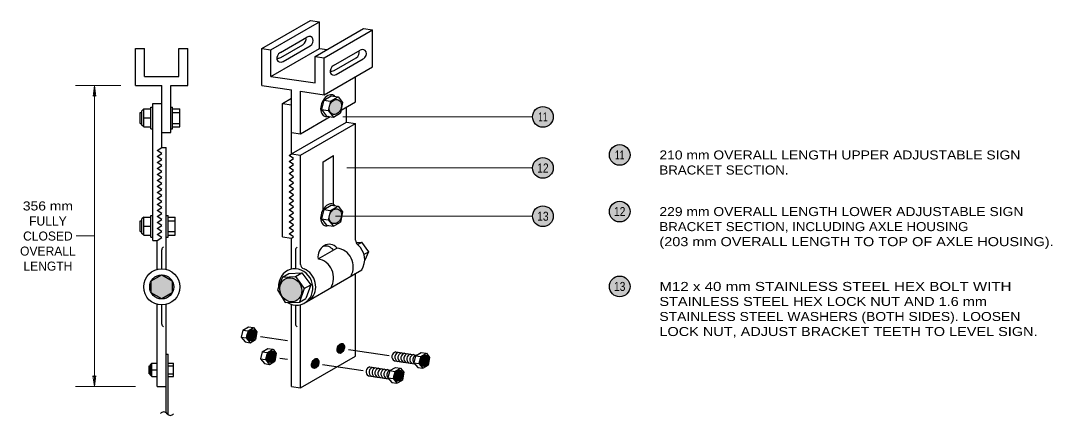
# Model space of a CAD drawing. Extents: x 312583 to 312853, y 144376 to 144586.
# Drawn here: x 312635.8 to 312721.6, y 144491.8 to 144524.7 of the extents above; entities that cross this region are included whole.
import ezdxf
from ezdxf.enums import TextEntityAlignment as Align

# ---------------------------------------------------------------- set-up
doc = ezdxf.new("R2010")
doc.units = 0
doc.header["$LTSCALE"] = 0.3
doc.layers.add('1', color=7, linetype='Continuous', lineweight=25)
doc.layers.add('2', color=7, linetype='Continuous', lineweight=13)

msp = doc.modelspace()

# ---------------------------------------------------------------- hatches: boundary and pattern name
at = {"layer": '1'}
h = msp.add_hatch(color=256, dxfattribs=at)
edge = h.paths.add_edge_path()
edge.add_ellipse((312661.9638, 144517.4761), major_axis=(0.2406, 0.5922), ratio=0.761491, start_angle=0, end_angle=360)
h = msp.add_hatch(color=256, dxfattribs=at)
edge = h.paths.add_edge_path()
edge.add_ellipse((312661.9638, 144508.3941), major_axis=(0.2406, 0.5922), ratio=0.761491, start_angle=0, end_angle=360)
for points in [[(312648.5336, 144502.5181, 1), (312646.5336, 144502.5181, 1)], [(312647.5336, 144503.5181), (312648.3997, 144503.0181), (312648.3997, 144502.0181), (312647.5336, 144501.5181), (312646.6676, 144502.0181), (312646.6676, 144503.0181)]]:
    msp.add_hatch(color=256, dxfattribs=at).paths.add_polyline_path(points)
h = msp.add_hatch(color=256, dxfattribs=at)
edge = h.paths.add_edge_path()
edge.add_ellipse((312658.2586, 144502.281), major_axis=(-0.3821, 0.9403), ratio=0.8873452, start_angle=0, end_angle=360)
h = msp.add_hatch(color=256, dxfattribs=at)
edge = h.paths.add_edge_path()
edge.add_ellipse((312655.0001, 144498.5047), major_axis=(0.1805, 0.4441), ratio=0.761491, start_angle=0, end_angle=360)
h = msp.add_hatch(color=256, dxfattribs=at)
edge = h.paths.add_edge_path()
edge.add_ellipse((312655.0001, 144498.5047), major_axis=(0.11, 0.2708), ratio=0.6087617, start_angle=0, end_angle=360)
h = msp.add_hatch(color=256, dxfattribs=at)
edge = h.paths.add_edge_path()
edge.add_ellipse((312662.4171, 144497.4067), major_axis=(0.1639, 0.4034), ratio=0.649846, start_angle=0, end_angle=360)
h = msp.add_hatch(color=256, dxfattribs=at)
edge = h.paths.add_edge_path()
edge.add_ellipse((312656.6117, 144496.7038), major_axis=(0.1805, 0.4441), ratio=0.761491, start_angle=0, end_angle=360)
h = msp.add_hatch(color=256, dxfattribs=at)
edge = h.paths.add_edge_path()
edge.add_ellipse((312656.6117, 144496.7038), major_axis=(0.11, 0.2708), ratio=0.6087617, start_angle=0, end_angle=360)
h = msp.add_hatch(color=256, dxfattribs=at)
edge = h.paths.add_edge_path()
edge.add_ellipse((312660.2921, 144496.159), major_axis=(0.1639, 0.4034), ratio=0.649846, start_angle=0, end_angle=360)
h = msp.add_hatch(color=256, dxfattribs=at)
edge = h.paths.add_edge_path()
edge.add_ellipse((312669.3588, 144496.3789), major_axis=(0.1805, 0.4441), ratio=0.761491, start_angle=0, end_angle=360)
h = msp.add_hatch(color=256, dxfattribs=at)
edge = h.paths.add_edge_path()
edge.add_ellipse((312667.2051, 144495.1355), major_axis=(0.1805, 0.4441), ratio=0.761491, start_angle=0, end_angle=360)
at = {"layer": '2'}
for points in [[(312680.0731, 144516.654, 1), (312678.3539, 144516.654, 1)], [(312686.4534, 144513.4875, 1), (312684.7342, 144513.4875, 1)], [(312680.0731, 144512.4048, 1), (312678.3539, 144512.4048, 1)], [(312680.0731, 144508.3941, 1), (312678.3539, 144508.3941, 1)], [(312686.4534, 144508.7813, 1), (312684.7342, 144508.7813, 1)], [(312686.4534, 144502.5587, 1), (312684.7342, 144502.5587, 1)]]:
    msp.add_hatch(color=256, dxfattribs=at).paths.add_polyline_path(points)

# ---------------------------------------------------------------- linework, layer by layer
at = {"layer": '1'}
for p, q in [((312655.858, 144522.3287), (312659.8879, 144524.6554)), ((312656.608, 144522.2176), (312660.638, 144524.5443)), ((312659.8879, 144524.6554), (312660.638, 144524.5443)), ((312660.638, 144522.3421), (312660.638, 144524.5443)), ((312660.2841, 144521.6731), (312664.3142, 144523.9999)), ((312664.3142, 144523.9999), (312665.0641, 144523.8888)), ((312657.3943, 144522.0035), (312659.5982, 144523.2759)), ((312645.3586, 144519.2653), (312645.3586, 144522.3287)), ((312645.3586, 144522.3287), (312646.1086, 144522.3287)), ((312646.1086, 144520.0153), (312646.1086, 144522.3287)), ((312648.9586, 144520.0153), (312648.9586, 144522.3287)), ((312648.9586, 144522.3287), (312649.7086, 144522.3287)), ((312649.7086, 144519.2653), (312649.7086, 144522.3287)), ((312655.858, 144519.2653), (312655.858, 144522.3287)), ((312655.858, 144522.3287), (312656.608, 144522.2176)), ((312656.608, 144520.0153), (312660.638, 144522.3421)), ((312656.608, 144520.0153), (312656.608, 144522.2176)), ((312657.4283, 144521.5902), (312659.2663, 144522.6513)), ((312657.6159, 144521.2654), (312659.8633, 144522.5629)), ((312660.638, 144522.3421), (312661.2785, 144522.2472)), ((312661.8204, 144520.9174), (312664.0244, 144522.1899)), ((312660.2841, 144519.4709), (312660.2841, 144521.6731)), ((312661.0341, 144518.4987), (312661.0341, 144521.5621)), ((312661.8545, 144520.5041), (312663.6924, 144521.5652)), ((312662.042, 144520.1793), (312664.2894, 144521.4768)), ((312645.3586, 144519.2653), (312647.5336, 144519.2653)), ((312646.1086, 144520.0153), (312648.9586, 144520.0153)), ((312648.2836, 144519.2653), (312649.7086, 144519.2653)), ((312655.858, 144519.2653), (312658.3203, 144518.9007)), ((312656.608, 144520.0153), (312660.2841, 144519.4709)), ((312663.6493, 144517.8979), (312663.6493, 144520.0086)), ((312658.3203, 144513.5713), (312658.3203, 144518.9007)), ((312659.0703, 144515.2542), (312659.0703, 144518.7896)), ((312659.0703, 144518.7896), (312661.0341, 144518.4987)), ((312661.0035, 144518.0396), (312661.6293, 144518.4009)), ((312661.6292, 144518.4009), (312662.185, 144518.3186)), ((312646.7836, 144517.7653), (312647.5336, 144517.7653)), ((312646.7836, 144506.3653), (312646.7836, 144517.7653)), ((312657.5703, 144517.7653), (312658.3203, 144518.1983)), ((312657.5703, 144517.7653), (312658.3203, 144517.6543)), ((312657.5703, 144506.6824), (312657.5703, 144517.7653)), ((312661.0035, 144518.0396), (312660.8034, 144517.2575)), ((312662.4389, 144517.1991), (312663.6493, 144517.8979)), ((312645.7336, 144516.1153), (312645.7336, 144517.0153)), ((312645.7336, 144517.0153), (312645.8836, 144517.0153)), ((312646.0336, 144517.3153), (312645.8836, 144517.1653)), ((312645.8836, 144515.9653), (312645.8836, 144517.1653)), ((312646.0336, 144515.8153), (312646.0336, 144517.3153)), ((312646.0336, 144517.3153), (312646.6336, 144517.3153)), ((312648.2836, 144517.4653), (312648.4336, 144517.4653)), ((312648.4336, 144515.6653), (312648.4336, 144517.4653)), ((312648.4336, 144517.3153), (312649.0336, 144517.3153)), ((312648.4336, 144517.0153), (312649.0336, 144517.0153)), ((312649.0336, 144515.8153), (312649.0336, 144517.3153)), ((312659.0703, 144515.2542), (312661.538, 144516.679)), ((312660.8034, 144517.2575), (312661.3696, 144517.1737)), ((312661.8044, 144516.6395), (312662.4029, 144516.9851)), ((312645.7336, 144516.1153), (312645.8836, 144516.1153)), ((312646.0336, 144515.8153), (312645.8836, 144515.9653)), ((312646.0336, 144516.5653), (312646.6336, 144516.5653)), ((312646.0336, 144515.8153), (312646.6336, 144515.8153)), ((312648.4336, 144516.1153), (312649.0336, 144516.1153)), ((312648.4336, 144515.8153), (312649.0336, 144515.8153)), ((312662.8993, 144516.2149), (312663.6493, 144516.1039)), ((312663.6493, 144506.3962), (312663.6493, 144516.1039)), ((312646.6336, 144515.6653), (312646.7836, 144515.6653)), ((312648.2836, 144515.6653), (312648.4336, 144515.6653)), ((312658.3203, 144515.3653), (312659.0703, 144515.2542)), ((312647.5336, 144514.1153), (312647.9086, 144514.1153)), ((312647.9086, 144503.9704), (312647.9086, 144514.1153)), ((312659.0703, 144504.3901), (312659.0703, 144513.4602)), ((312661.813, 144509.3692), (312661.813, 144513.4318)), ((312661.0035, 144508.9576), (312660.8034, 144508.1755)), ((312661.0035, 144508.9576), (312661.6293, 144509.3189)), ((312661.6292, 144509.3189), (312662.185, 144509.2366)), ((312646.0336, 144508.3153), (312645.8836, 144508.1653)), ((312645.8836, 144506.9653), (312645.8836, 144508.1653)), ((312646.0336, 144506.8153), (312646.0336, 144508.3153)), ((312646.0336, 144508.3153), (312646.6336, 144508.3153)), ((312647.9086, 144508.4653), (312648.0586, 144508.4653)), ((312648.0586, 144506.6653), (312648.0586, 144508.4653)), ((312648.0586, 144508.3153), (312648.6586, 144508.3153)), ((312648.6586, 144506.8153), (312648.6586, 144508.3153)), ((312660.8034, 144508.1755), (312661.3696, 144508.0917)), ((312645.7336, 144507.1153), (312645.7336, 144508.0153)), ((312645.7336, 144508.0153), (312645.8836, 144508.0153)), ((312646.0336, 144507.5653), (312646.6336, 144507.5653)), ((312648.0586, 144508.0153), (312648.6586, 144508.0153)), ((312661.8044, 144507.5575), (312662.4029, 144507.9031)), ((312645.7336, 144507.1153), (312645.8836, 144507.1153)), ((312646.0336, 144506.8153), (312645.8836, 144506.9653)), ((312646.0336, 144506.8153), (312646.6336, 144506.8153)), ((312646.6336, 144506.6653), (312646.7836, 144506.6653)), ((312647.9086, 144506.6653), (312648.0586, 144506.6653)), ((312648.0586, 144507.1153), (312648.6586, 144507.1153)), ((312648.0586, 144506.8153), (312648.6586, 144506.8153)), ((312657.5703, 144506.6824), (312658.3203, 144506.5713)), ((312658.3203, 144503.9925), (312658.3203, 144506.5713)), ((312646.7836, 144506.3653), (312647.1586, 144506.3653)), ((312647.1586, 144503.9704), (312647.1586, 144506.3653)), ((312647.5336, 144504.0181), (312647.5336, 144505.606)), ((312658.6501, 144505.5937), (312658.6501, 144504.0181)), ((312660.5289, 144504.848), (312662.097, 144505.7533)), ((312663.6876, 144506.2093), (312664.1458, 144506.2322)), ((312663.8062, 144506.0362), (312664.1458, 144506.2322)), ((312664.1458, 144506.2322), (312664.7292, 144505.4317)), ((312664.3439, 144505.2093), (312664.7292, 144505.4317)), ((312664.7292, 144505.4317), (312664.4027, 144504.7538)), ((312659.5549, 144501.2856), (312664.1529, 144503.9403)), ((312657.5627, 144503.3221), (312658.0998, 144503.6322)), ((312658.0998, 144503.6322), (312659.1831, 144503.6863)), ((312658.646, 144503.3762), (312659.1831, 144503.6863)), ((312663.6493, 144496.7589), (312663.6493, 144503.6495)), ((312663.6493, 144502.9771), (312663.6493, 144503.6495)), ((312659.3766, 144502.3737), (312659.9137, 144502.6838)), ((312658.9737, 144501.2433), (312659.5108, 144501.5534)), ((312647.1586, 144494.2385), (312647.1586, 144501.0657)), ((312647.5336, 144499.4302), (312647.5336, 144501.0181)), ((312647.9086, 144492.0507), (312647.9086, 144501.0657)), ((312658.3203, 144494.2263), (312658.3203, 144501.0717)), ((312658.6501, 144501.0082), (312658.6501, 144499.4326)), ((312659.0703, 144494.1152), (312659.0703, 144501.0461)), ((312654.2798, 144498.9274), (312654.1298, 144498.3408)), ((312654.2798, 144498.9274), (312654.7492, 144499.1984)), ((312654.7492, 144499.1984), (312655.166, 144499.1366)), ((312654.1298, 144498.3408), (312654.5545, 144498.2779)), ((312654.8806, 144497.8773), (312655.3294, 144498.1365)), ((312655.7474, 144498.3941), (312657.9988, 144498.0608)), ((312655.8914, 144497.1265), (312655.7414, 144496.5399)), ((312655.8914, 144497.1265), (312656.3608, 144497.3975)), ((312656.3608, 144497.3975), (312656.7776, 144497.3357)), ((312663.0431, 144497.3141), (312666.4291, 144496.8129)), ((312666.9895, 144497.1089), (312668.7255, 144496.8518)), ((312668.6385, 144496.8016), (312669.1079, 144497.0726)), ((312669.1079, 144497.0726), (312669.5247, 144497.0108)), ((312646.7086, 144496.1885), (312646.5961, 144496.076)), ((312646.7086, 144495.0635), (312646.7086, 144496.1885)), ((312646.7086, 144496.1885), (312647.1586, 144496.1885)), ((312647.9086, 144496.9385), (312648.0586, 144496.9385)), ((312648.0586, 144491.8994), (312648.0586, 144496.9385)), ((312648.0586, 144496.1885), (312648.5086, 144496.1885)), ((312648.5086, 144495.0635), (312648.5086, 144496.1885)), ((312655.7414, 144496.5399), (312656.1661, 144496.477)), ((312656.4922, 144496.0764), (312656.941, 144496.3356)), ((312657.359, 144496.5932), (312657.9988, 144496.4985)), ((312666.8725, 144496.368), (312668.5684, 144496.1168)), ((312668.6385, 144496.8016), (312668.4885, 144496.215)), ((312668.4885, 144496.215), (312668.9132, 144496.1521)), ((312646.4836, 144495.2885), (312646.4836, 144495.9635)), ((312646.4836, 144495.9635), (312646.5961, 144495.9635)), ((312646.4836, 144495.2885), (312646.5961, 144495.2885)), ((312646.5961, 144495.176), (312646.5961, 144496.076)), ((312646.7086, 144495.626), (312647.1586, 144495.626)), ((312648.0586, 144495.9635), (312648.5086, 144495.9635)), ((312648.0586, 144495.2885), (312648.5086, 144495.2885)), ((312660.8894, 144496.0706), (312664.2754, 144495.5694)), ((312664.8358, 144495.8655), (312666.5718, 144495.6084)), ((312666.4848, 144495.5581), (312666.3348, 144494.9716)), ((312666.4848, 144495.5581), (312666.9542, 144495.8291)), ((312666.9542, 144495.8291), (312667.371, 144495.7674)), ((312669.2393, 144495.7515), (312669.6881, 144496.0107)), ((312646.7086, 144495.0635), (312646.5961, 144495.176)), ((312646.7086, 144495.0635), (312647.1586, 144495.0635)), ((312648.0586, 144495.0635), (312648.5086, 144495.0635)), ((312664.7188, 144495.1246), (312666.4147, 144494.8734)), ((312666.3348, 144494.9716), (312666.7595, 144494.9087)), ((312667.0856, 144494.5081), (312667.5344, 144494.7672)), ((312647.1586, 144494.2385), (312647.9086, 144494.2385))]:
    msp.add_line(p, q, dxfattribs=at)
for points in [[(312660.2841, 144521.6731), (312661.0341, 144521.5621), (312665.0641, 144523.8888)], [(312661.0341, 144518.4987), (312665.0641, 144520.8255), (312665.0641, 144523.8888)], [(312647.1586, 144506.3653), (312647.5336, 144506.6153), (312647.1586, 144506.8653), (312647.5336, 144507.1153), (312647.1586, 144507.3653), (312647.5336, 144507.6153), (312647.1586, 144507.8653), (312647.5336, 144508.1153), (312647.1586, 144508.3653), (312647.5336, 144508.6153), (312647.1586, 144508.8653), (312647.5336, 144509.1153), (312647.1586, 144509.3653), (312647.5336, 144509.6153), (312647.1586, 144509.8653), (312647.5336, 144510.1153), (312647.1586, 144510.3653), (312647.5336, 144510.6153), (312647.1586, 144510.8653), (312647.5336, 144511.1153), (312647.1586, 144511.3653), (312647.5336, 144511.6153), (312647.1586, 144511.8653), (312647.5336, 144512.1153), (312647.1586, 144512.3653), (312647.5336, 144512.6153), (312647.1586, 144512.8653), (312647.5336, 144513.1153), (312647.1586, 144513.3653), (312647.5336, 144513.6153), (312647.1586, 144513.8653), (312647.5336, 144514.1153), (312647.5336, 144519.2653)], [(312647.5336, 144515.3653), (312648.2836, 144515.3653), (312648.2836, 144519.2653)], [(312661.0035, 144518.0396), (312661.5697, 144517.9558), (312662.1955, 144518.3171)], [(312661.5697, 144517.9558), (312661.3696, 144517.1737), (312661.8044, 144516.6395)], [(312662.1955, 144518.3171), (312662.5489, 144517.8545), (312662.4029, 144516.9851)], [(312646.6336, 144515.6653), (312646.6336, 144517.4653), (312646.7836, 144517.4653)], [(312658.3203, 144513.5713), (312662.8993, 144516.2149), (312662.8993, 144517.4649)], [(312660.8034, 144517.2575), (312661.2382, 144516.7234), (312661.8044, 144516.6395)], [(312658.3203, 144513.5713), (312659.0703, 144513.4602), (312663.6493, 144516.1039)], [(312647.1586, 144506.3653), (312647.5336, 144506.6153), (312647.1586, 144506.8653), (312647.5336, 144507.1153), (312647.1586, 144507.3653), (312647.5336, 144507.6153), (312647.1586, 144507.8653), (312647.5336, 144508.1153), (312647.1586, 144508.3653), (312647.5336, 144508.6153), (312647.1586, 144508.8653), (312647.5336, 144509.1153), (312647.1586, 144509.3653), (312647.5336, 144509.6153), (312647.1586, 144509.8653), (312647.5336, 144510.1153), (312647.1586, 144510.3653), (312647.5336, 144510.6153), (312647.1586, 144510.8653), (312647.5336, 144511.1153), (312647.1586, 144511.3653), (312647.5336, 144511.6153), (312647.1586, 144511.8653), (312647.5336, 144512.1153), (312647.1586, 144512.3653), (312647.5336, 144512.6153), (312647.1586, 144512.8653), (312647.5336, 144513.1153), (312647.1586, 144513.3653), (312647.5336, 144513.6153), (312647.1586, 144513.8653), (312647.5336, 144514.1153)], [(312658.3203, 144506.5713), (312658.4882, 144506.6833), (312658.1132, 144506.9333), (312658.4882, 144507.1833), (312658.1132, 144507.4333), (312658.4882, 144507.6833), (312658.1132, 144507.9333), (312658.4882, 144508.1833), (312658.1132, 144508.4333), (312658.4882, 144508.6833), (312658.1132, 144508.9333), (312658.4882, 144509.1833), (312658.1132, 144509.4333), (312658.4882, 144509.6833), (312658.1132, 144509.9333), (312658.4882, 144510.1833), (312658.1132, 144510.4333), (312658.4882, 144510.6833), (312658.1132, 144510.9333), (312658.4882, 144511.1833), (312658.1132, 144511.4333), (312658.4882, 144511.6833), (312658.1132, 144511.9333), (312658.4882, 144512.1833), (312658.1132, 144512.4333), (312658.4882, 144512.6833), (312658.1132, 144512.9333), (312658.4882, 144513.1833), (312658.1132, 144513.4333), (312658.3203, 144513.5713)], [(312660.938, 144508.9288), (312660.938, 144512.9266), (312661.813, 144513.4318)], [(312661.0035, 144508.9576), (312661.5697, 144508.8738), (312662.1955, 144509.2351)], [(312662.1955, 144509.2351), (312662.5489, 144508.7725), (312662.4029, 144507.9031)], [(312646.6336, 144506.6653), (312646.6336, 144508.4653), (312646.7836, 144508.4653)], [(312660.8034, 144508.1755), (312661.2382, 144507.6414), (312661.8044, 144507.5575)], [(312661.5697, 144508.8738), (312661.3696, 144508.0917), (312661.8044, 144507.5575)], [(312657.5627, 144503.3221), (312657.163, 144502.2657), (312657.8019, 144501.2266), (312658.9737, 144501.2433)], [(312657.5627, 144503.3221), (312658.646, 144503.3762), (312659.3766, 144502.3737), (312658.9737, 144501.2433)], [(312659.1831, 144503.6863), (312659.9137, 144502.6838), (312659.5108, 144501.5534)], [(312654.2798, 144498.9274), (312654.7045, 144498.8645), (312655.1738, 144499.1355)], [(312654.7045, 144498.8645), (312654.5545, 144498.2779), (312654.8806, 144497.8773)], [(312655.1738, 144499.1355), (312655.4389, 144498.7886), (312655.3294, 144498.1365)], [(312654.1298, 144498.3408), (312654.4559, 144497.9402), (312654.8806, 144497.8773)], [(312655.8914, 144497.1265), (312656.3161, 144497.0636), (312656.7854, 144497.3346)], [(312656.3161, 144497.0636), (312656.1661, 144496.477), (312656.4922, 144496.0764)], [(312656.7854, 144497.3346), (312657.0505, 144496.9877), (312656.941, 144496.3356)], [(312668.6385, 144496.8016), (312669.0632, 144496.7387), (312669.5325, 144497.0097)], [(312669.5325, 144497.0097), (312669.7976, 144496.6628), (312669.6881, 144496.0107)], [(312655.7414, 144496.5399), (312656.0675, 144496.1393), (312656.4922, 144496.0764)], [(312658.3203, 144494.2263), (312659.0703, 144494.1152), (312663.6493, 144496.7589)], [(312668.4885, 144496.215), (312668.8146, 144495.8144), (312669.2393, 144495.7515)], [(312669.0632, 144496.7387), (312668.9132, 144496.1521), (312669.2393, 144495.7515)], [(312666.4848, 144495.5581), (312666.9095, 144495.4953), (312667.3788, 144495.7662)], [(312666.9095, 144495.4953), (312666.7595, 144494.9087), (312667.0856, 144494.5081)], [(312667.3788, 144495.7662), (312667.6439, 144495.4193), (312667.5344, 144494.7672)], [(312666.3348, 144494.9716), (312666.6609, 144494.571), (312667.0856, 144494.5081)]]:
    msp.add_lwpolyline(points, dxfattribs=at)
msp.add_lwpolyline([(312647.5336, 144503.5181), (312648.3997, 144503.0181), (312648.3997, 144502.0181), (312647.5336, 144501.5181), (312646.6676, 144502.0181), (312646.6676, 144503.0181)], close=True, dxfattribs=at)
for radius in [1.5, 1]:
    msp.add_circle((312647.5336, 144502.5181), radius, dxfattribs=at)
for centre, radius, start, end in [((312664.147, 144506.3981), 0.4967, 180.22652, 231.68552), ((312659.4506, 144504.3831), 0.3804, 178.94586, 256.44003), ((312667.0644, 144496.7174), 0.3986, 100.84228, 241.21763), ((312667.3117, 144496.6807), 0.3986, 100.84228, 241.21763), ((312667.559, 144496.6441), 0.3986, 100.84228, 241.21763), ((312667.8063, 144496.6075), 0.3986, 100.84228, 241.21763), ((312668.0536, 144496.5709), 0.3986, 100.84228, 241.21763), ((312668.3009, 144496.5343), 0.3986, 100.84228, 241.21763), ((312668.5482, 144496.4977), 0.3986, 100.84228, 241.21763), ((312668.7955, 144496.4611), 0.3986, 100.84228, 218.70473), ((312664.9107, 144495.4739), 0.3986, 100.84228, 241.21763), ((312665.158, 144495.4373), 0.3986, 100.84228, 241.21763), ((312665.4053, 144495.4007), 0.3986, 100.84228, 241.21763), ((312665.6526, 144495.3641), 0.3986, 100.84228, 241.21763), ((312665.8999, 144495.3274), 0.3986, 100.84228, 241.21763), ((312666.1472, 144495.2908), 0.3986, 100.84228, 241.21763), ((312666.3945, 144495.2542), 0.3986, 100.84228, 241.21763), ((312666.6468, 144495.2168), 0.3986, 100.84228, 218.17149), ((312647.7014, 144491.7926), 0.3323, 33.87567, 144.14149), ((312648.2511, 144492.1802), 0.3405, 216.4613, 322.83048)]:
    msp.add_arc(centre, radius, start, end, dxfattribs=at)
for centre, major_axis, ratio, start_param, end_param in [((312659.1155, 144522.9965), (0.3145, 0.3553), 0.764015, 4.3716846, 5.8725332), ((312659.7125, 144522.9081), (0.3145, 0.3553), 0.764015, 4.3716846, 7.4201263), ((312657.5142, 144521.6394), (0.3145, 0.3553), 0.764015, 1.1518111, 4.2474694), ((312663.5417, 144521.9104), (0.3145, 0.3553), 0.764015, 4.3716846, 5.8725332), ((312664.1387, 144521.822), (0.3145, 0.3553), 0.764015, 4.3716846, 7.4201263), ((312657.3267, 144521.9642), (0.3145, 0.3553), 0.764015, 3.4232596, 4.2474694), ((312661.9404, 144520.5534), (0.3145, 0.3553), 0.764015, 1.1518111, 4.2474694), ((312661.7528, 144520.8782), (0.3145, 0.3553), 0.764015, 3.4232596, 4.2474694), ((312661.4164, 144517.5913), (-0.357, -0.8786), 0.649846, 2.8294508, 6.7628931), ((312661.4164, 144508.5093), (-0.357, -0.8786), 0.649846, 2.8294508, 6.7628931), ((312647.9672, 144505.6457), (0.4336, 0.0397), 0.649846, 2.238563, 3.141509), ((312659.0837, 144505.6334), (0.4336, 0.0397), 0.649846, 2.238563, 3.141509), ((312661.4219, 144505.0506), (0.1817, 0.9986), 0.887345, 5.6414307, 8.2157378), ((312661.0993, 144504.9085), (0.1817, 0.9986), 0.887345, 5.600291, 6.6323001), ((312662.0318, 144504.2536), (-0.5733, 1.4109), 0.924918, 3.772746, 5.8235033), ((312662.9776, 144504.8593), (-0.5733, 1.4109), 0.924918, 3.6971351, 5.2200889), ((312660.3924, 144503.3577), (-0.5733, 1.4109), 0.924918, 3.7094114, 5.7733759), ((312658.6648, 144502.5123), (-0.5733, 1.4109), 0.924918, 2.2297812, 7.5167148), ((312658.9096, 144502.6118), (-0.5733, 1.4109), 0.924918, 3.5253261, 5.5467497), ((312647.9672, 144499.3905), (0.4336, -0.0397), 0.649846, 3.1416763, 4.0446223), ((312659.0837, 144499.3929), (0.4336, -0.0397), 0.649846, 3.1416763, 4.0446223), ((312662.1302, 144497.5443), (0.1639, 0.4034), 0.649846, 3.6987557, 5.6461557), ((312660.0149, 144496.27), (0.1639, 0.4034), 0.649846, 3.701042, 5.7298077)]:
    msp.add_ellipse(centre, major_axis=major_axis, ratio=ratio, start_param=start_param, end_param=end_param, dxfattribs=at)
for centre, major_axis, ratio in [((312661.9638, 144517.4761), (0.2406, 0.5922), 0.761491), ((312661.9638, 144508.3941), (0.2406, 0.5922), 0.761491), ((312658.2586, 144502.281), (-0.3821, 0.9403), 0.887345), ((312655.0001, 144498.5047), (0.1805, 0.4441), 0.761491), ((312655.0001, 144498.5047), (0.11, 0.2708), 0.608762), ((312662.4171, 144497.4067), (0.1639, 0.4034), 0.649846), ((312656.6117, 144496.7038), (0.1805, 0.4441), 0.761491), ((312656.6117, 144496.7038), (0.11, 0.2708), 0.608762), ((312660.2921, 144496.159), (0.1639, 0.4034), 0.649846), ((312669.3588, 144496.3789), (0.1805, 0.4441), 0.761491), ((312667.2051, 144495.1355), (0.1805, 0.4441), 0.761491)]:
    msp.add_ellipse(centre, major_axis=major_axis, ratio=ratio, dxfattribs=at)
at = {"layer": '2'}
for p, q in [((312640.3586, 144519.2653), (312644.1335, 144519.2653)), ((312641.9374, 144519.2653), (312641.9374, 144494.2385)), ((312662.5871, 144516.654), (312678.3539, 144516.654)), ((312662.9059, 144512.4048), (312678.3539, 144512.4048)), ((312661.9638, 144508.3941), (312678.3539, 144508.3941)), ((312641.9374, 144506.7519), (312640.4275, 144506.7519)), ((312640.3586, 144494.2385), (312645.3634, 144494.2385))]:
    msp.add_line(p, q, dxfattribs=at)
for points in [[(312641.8274, 144518.3653), (312641.9374, 144519.2653), (312642.0574, 144518.3653), (312641.9374, 144518.4553)], [(312642.0474, 144495.1385), (312641.9374, 144494.2385), (312641.8174, 144495.1385), (312641.9374, 144495.0485)]]:
    msp.add_lwpolyline(points, close=True, dxfattribs=at)
at = {"layer": '2', "lineweight": 25}
for centre in [(312679.2135, 144516.654), (312685.5938, 144513.4875), (312679.2135, 144512.4048), (312679.2135, 144508.3941), (312685.5938, 144508.7813), (312685.5938, 144502.5587)]:
    msp.add_circle(centre, 0.8596, dxfattribs=at)

# ---------------------------------------------------------------- texts
at = {"layer": '2'}
for s, width, p in [('11', 0.7, (312679.2135, 144516.279)), ('11', 0.7, (312685.5938, 144513.1125)), ('12', 0.85, (312679.2135, 144512.0298)), ('356 mm', 1.15, (312638.0746, 144508.8732)), ('12', 0.85, (312685.5938, 144508.4063)), ('13', 0.85, (312679.2135, 144508.0191)), ('13', 0.85, (312685.5938, 144502.1837))]:
    msp.add_text(s, height=0.75, dxfattribs=dict(at, width=width)).set_placement(p, align=Align.CENTER)
for s, width, p in [('210 mm OVERALL LENGTH UPPER ADJUSTABLE SIGN', 1.15, (312688.8942, 144513.1125)), ('BRACKET SECTION.', 1.1, (312688.8942, 144511.8625)), ('229 mm OVERALL LENGTH LOWER ADJUSTABLE SIGN', 1.15, (312688.8942, 144508.4063)), ('BRACKET SECTION, INCLUDING AXLE HOUSING', 1.1, (312688.8942, 144507.1563)), ('(203 mm OVERALL LENGTH TO TOP OF AXLE HOUSING).', 1.2, (312688.8942, 144505.9063)), ('M12 x 40 mm STAINLESS STEEL HEX BOLT WITH', 1.25, (312688.8942, 144502.1837)), ('STAINLESS STEEL HEX LOCK NUT AND 1.6 mm', 1.2, (312688.8942, 144500.9337)), ('STAINLESS STEEL WASHERS (BOTH SIDES). LOOSEN', 1.15, (312688.8942, 144499.6837)), ('LOCK NUT, ADJUST BRACKET TEETH TO LEVEL SIGN.', 1.2, (312688.8942, 144498.4337))]:
    msp.add_text(s, height=0.75, dxfattribs=dict(at, width=width)).set_placement(p)
for s, p in [('FULLY', (312638.0746, 144507.6232)), ('CLOSED', (312638.0746, 144506.3732)), ('OVERALL', (312638.0746, 144505.1232)), ('LENGTH', (312638.0746, 144503.8732))]:
    msp.add_text(s, height=0.75, dxfattribs=at).set_placement(p, align=Align.CENTER)

doc.saveas('drawing.dxf')
